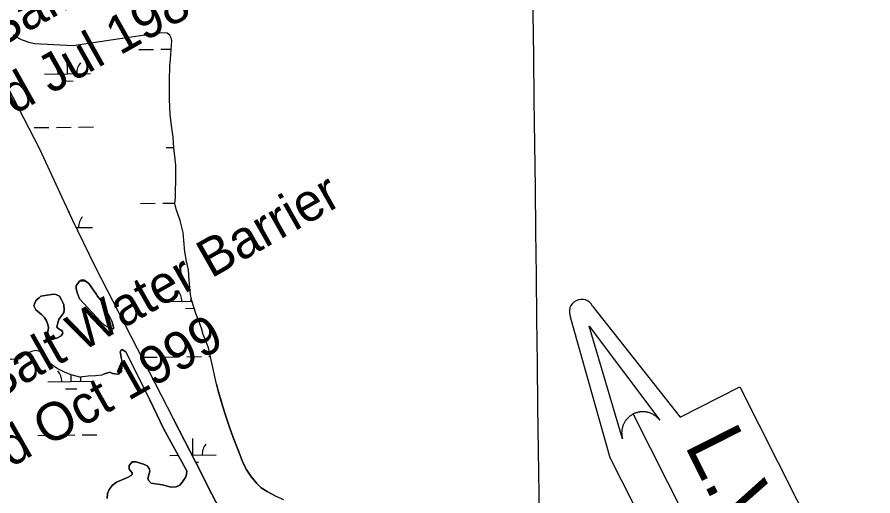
# Model space of a CAD drawing. Extents: x 3684037 to 3722149, y 433263 to 459021.
# Drawn here: x 3713579 to 3715429, y 439834 to 440869 of the extents above; entities that cross this region are included whole.
import ezdxf

# ---------------------------------------------------------------- set-up
doc = ezdxf.new("R2010")
doc.units = 0
for name, color, linetype in [('V-GRID-MAJR', 7, 'Continuous'), ('V-RRAP-SILL-IDEN', 7, 'Continuous'), ('V-TOPO-SHOR', 7, 'Continuous'), ('V-TOPO-WATR-IDEN', 7, 'Continuous'), ('V-WETL-SWMP', 7, 'Continuous')]:
    doc.layers.add(name, color=color, linetype=linetype)

msp = doc.modelspace()

# ---------------------------------------------------------------- linework, layer by layer
at = {"layer": 'V-GRID-MAJR'}
msp.add_spline([(3714717.7800000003, 438985.321), (3714645.519, 445043.8), (3714573.235, 451104.20900000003), (3714500.951, 457164.625), (3714500.9280000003, 457166.547)], degree=3, dxfattribs=at)
at = {"layer": 'V-TOPO-SHOR'}
for points in [[(3714010.265, 440075.83), (3713993.5160000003, 440153.73600000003), (3713987.551, 440169.196), (3713981.585, 440182.871), (3713977.9990000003, 440196.547), (3713972.0330000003, 440211.414), (3713965.469, 440228.656), (3713957.109, 440256.009), (3713954.119, 440269.094), (3713951.702, 440300.619), (3713949.892, 440322.624), (3713945.7060000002, 440341.656), (3713942.112, 440361.876), (3713939.703, 440386.264), (3713938.4930000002, 440403.512), (3713931.919, 440429.68), (3713922.967, 440454.05700000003), (3713920.573, 440465.952), (3713921.7460000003, 440479.04000000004), (3713922.877, 440529.606), (3713922.258, 440549.234), (3713921.054, 440561.724), (3713918.052, 440586.11), (3713916.833, 440609.31), (3713913.8370000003, 440629.529), (3713910.233, 440658.079), (3713909.004, 440691.985), (3713908.955, 440733.029), (3713909.514, 440762.77400000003), (3713911.279, 440778.243), (3713913.612, 440818.101), (3713912.416, 440824.049), (3713910.0300000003, 440828.804), (3713909.434, 440829.994), (3713905.2660000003, 440832.961), (3713903.48, 440834.14900000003), (3713892.177, 440834.731), (3713816.0470000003, 440823.934), (3713700.665, 440807.14), (3713616.785, 440811.206), (3713607.86, 440813.57300000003), (3713588.815, 440820.096), (3713570.9590000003, 440830.186)], [(3713523.423, 440785.515), (3713627.7600000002, 440584.576), (3713698.1350000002, 440431.781), (3713747.603, 440330.726), (3713916.612, 440001.09500000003)], [(3713750.9760000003, 440269.68200000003), (3713734.719, 440292.844), (3713724.278, 440300.367), (3713717.903, 440300.359), (3713713.27, 440297.457), (3713707.485, 440288.175), (3713706.913, 440281.8), (3713709.823, 440271.371), (3713714.474, 440259.786), (3713760.319, 440210.576), (3713768.441, 440203.052), (3713776.56, 440198.425), (3713779.46, 440197.268), (3713782.937, 440196.113), (3713787.576, 440194.96), (3713787.576, 440196.119), (3713787.574, 440197.858), (3713784.659, 440210.025), (3713780.0100000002, 440220.452), (3713773.623, 440232.03500000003), (3713766.074, 440244.778), (3713760.264, 440256.943), (3713752.717, 440266.786), (3713750.9760000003, 440269.68200000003)], [(3713658.242, 440270.151), (3713640.279, 440267.23), (3713631.008, 440265.481), (3713626.955, 440262), (3713620.586, 440257.355), (3713617.696, 440250.977), (3713615.964, 440245.179), (3713620.0330000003, 440235.91000000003), (3713627.574, 440229.545), (3713632.794, 440225.494), (3713638.598, 440219.704), (3713642.663, 440212.755), (3713645.569, 440204.643), (3713647.316, 440197.692), (3713646.167, 440188.99700000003), (3713646.174, 440185.51900000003), (3713649.657, 440178.568), (3713651.9820000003, 440173.936), (3713656.041, 440172.201), (3713659.5160000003, 440173.364), (3713666.469, 440175.691), (3713674.577, 440179.75800000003), (3713678.049, 440186.137), (3713677.465, 440189.033), (3713675.722, 440191.929), (3713672.824, 440193.08400000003), (3713667.022, 440197.135), (3713665.281, 440199.452), (3713666.434, 440205.249), (3713669.3200000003, 440215.684), (3713675.685, 440223.227), (3713678, 440226.706), (3713680.3140000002, 440230.188), (3713681.467, 440235.404), (3713680.293, 440247.57300000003), (3713675.644, 440258), (3713670.9990000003, 440265.528), (3713665.2, 440268.42), (3713662.879, 440269.577), (3713658.242, 440270.151)], [(3713768.642, 440098.106), (3713762.781, 440095.167), (3713749.102, 440093.365), (3713733.04, 440092.753), (3713715.197, 440090.35000000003), (3713696.1550000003, 440095.683), (3713683.6580000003, 440100.427), (3713665.802, 440109.327), (3713649.727, 440120.612), (3713640.196, 440132.498), (3713631.256, 440145.575), (3713619.355, 440148.534), (3713610.436, 440146.14400000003), (3713598.545, 440140.776), (3713585.471, 440130.64900000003), (3713567.627, 440128.843), (3713553.94, 440133.586), (3713541.443, 440137.733), (3713534.8910000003, 440143.08), (3713536.071, 440152.599), (3713547.968, 440153.208), (3713552.127, 440155.594), (3713557.4790000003, 440158.57300000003)], [(3713768.642, 440098.106), (3713779.65, 440101.596), (3713786.0270000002, 440098.706), (3713790.664, 440097.553), (3713795.882, 440096.98), (3713799.937, 440098.723), (3713805.148, 440102.786), (3713805.715, 440113.218), (3713806.282, 440124.231), (3713804.531, 440133.50200000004), (3713802.784, 440141.614), (3713802.201, 440145.669), (3713803.935, 440148.569), (3713805.6720000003, 440149.73), (3713806.251, 440150.31200000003), (3713808.572, 440149.155), (3713814.372, 440145.106), (3713866.6550000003, 440041.42600000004), (3713896.804, 439978.39)], [(3714010.265, 440075.83), (3714014.281, 440061.443), (3714019.096, 440044.723), (3714024.308, 440026.838), (3714029.916, 440008.566), (3714038.7060000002, 439982.523), (3714046.685, 439959.983), (3714057.043, 439932.788), (3714066.984, 439908.70300000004), (3714074.531, 439891.617), (3714084.79, 439876.5), (3714097.389, 439861.015), (3714107.211, 439851.353), (3714119.7490000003, 439843.27), (3714137.364, 439834.06200000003), (3714155.356, 439826.414)], [(3714060.322, 439723.427), (3714000.486, 439837.82), (3713965.748, 439906.246), (3713916.612, 440001.09500000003)], [(3713896.804, 439978.39), (3713943.3140000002, 439893.337), (3713946.2630000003, 439888.27), (3713945.591, 439881.358), (3713944.188, 439875.16500000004), (3713937.008, 439864.2), (3713930.8850000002, 439857.24100000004), (3713923.2800000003, 439853.544), (3713912.014, 439853.088), (3713896.714, 439856.96), (3713888.7, 439858.713), (3713877.7800000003, 439860.442), (3713869.406, 439861.826), (3713863.911, 439866.871), (3713862.0530000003, 439871.581), (3713864.5330000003, 439879.599), (3713866.649, 439887.617), (3713865.146, 439893.42100000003), (3713860.376, 439898.836), (3713852.708, 439902.77), (3713845.784, 439904.896), (3713837.037, 439907.368), (3713828.31, 439907.661), (3713821.833, 439899.608), (3713821.894, 439891.973), (3713824.468, 439888.36), (3713828.505, 439884.031), (3713828.534, 439880.396), (3713826.011, 439877.83), (3713818.046, 439873.764), (3713794.4960000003, 439863.754), (3713784.741, 439856.403), (3713778.628, 439847.99), (3713775.0670000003, 439839.237), (3713774.426, 439828.688)]]:
    msp.add_lwpolyline(points, dxfattribs=at)
at = {"layer": 'V-TOPO-WATR-IDEN'}
msp.add_line((3714911.4286129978, 440011.0038726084), (3715249.903243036, 439340.3800102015), dxfattribs=at)
for points in [[(3714823.368048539, 440244.32581142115), (3715012.440461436, 440004.4185395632), (3715141.6419531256, 440069.6279592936), (3715429.3485540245, 439499.58574517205), (3715300.1470623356, 439434.37632544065), (3715385.3012234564, 439130.94978800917)], [(3715337.9638074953, 439107.058071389), (3715139.659959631, 439365.2558781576), (3715048.004676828, 439546.855397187), (3714909.3357019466, 439476.8676341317), (3714824.145443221, 439645.65779589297), (3714962.8144181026, 439715.64555894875), (3714861.510045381, 439916.3631258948), (3714776.0306325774, 440220.43409480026)]]:
    msp.add_lwpolyline(points, dxfattribs=at)
msp.add_lwpolyline([(3714888.1532795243, 439957.2509763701), (3714815.7278187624, 440200.6222208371), (3714968.500426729, 439997.80138867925), (3714965.564487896, 440001.29808907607), (3714962.4127743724, 440004.3767245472), (3714961.0620843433, 440005.53150026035), (3714959.837528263, 440006.5029443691), (3714958.306520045, 440007.62215886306), (3714956.78795493, 440008.6434796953), (3714955.43981526, 440009.47693976), (3714953.5501225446, 440010.5411389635), (3714951.4659689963, 440011.5844819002), (3714950.2786089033, 440012.1193587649), (3714948.7265896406, 440012.76086672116), (3714946.646862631, 440013.5191256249), (3714945.006765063, 440014.03552877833), (3714943.2205280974, 440014.5252200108), (3714942.0334510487, 440014.8065260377), (3714940.7202833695, 440015.0813203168), (3714939.1065625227, 440015.36236306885), (3714937.613190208, 440015.5714094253), (3714936.1173289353, 440015.72879288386), (3714934.88869454, 440015.82278236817), (3714933.0583915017, 440015.90042119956), (3714931.3034948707, 440015.9052237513), (3714929.9009657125, 440015.8610399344), (3714928.254491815, 440015.7542225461), (3714926.828174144, 440015.61402124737), (3714925.5676337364, 440015.45163550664), (3714924.5928153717, 440015.3023994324), (3714923.108631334, 440015.03049872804), (3714921.595814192, 440014.702141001), (3714920.1743339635, 440014.3459522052), (3714918.740315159, 440013.9347085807), (3714917.424402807, 440013.5125052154), (3714916.0007995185, 440013.007385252), (3714914.8459964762, 440012.5556008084), (3714913.214496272, 440011.8565011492), (3714911.4286129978, 440011.0038726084), (3714910.8655370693, 440010.7146412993), (3714910.0494454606, 440010.2775475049), (3714909.091534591, 440009.73527150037), (3714908.1745485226, 440009.1918077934), (3714907.299175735, 440008.6424631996), (3714906.4566931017, 440008.0878757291), (3714905.4771600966, 440007.408670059), (3714904.804819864, 440006.91979265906), (3714903.8375785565, 440006.1829422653), (3714902.953425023, 440005.47122495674), (3714902.3522467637, 440004.96785709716), (3714900.845930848, 440003.6245653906), (3714900.0658799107, 440002.8796984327), (3714899.5399061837, 440002.35715954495), (3714898.6892610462, 440001.4758495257), (3714897.952364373, 440000.67211229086), (3714897.2029291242, 439999.81332022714), (3714896.3441664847, 439998.7716524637), (3714895.5677400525, 439997.7765813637), (3714894.983065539, 439996.98750407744), (3714894.495944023, 439996.3014300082), (3714893.854843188, 439995.35449655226), (3714893.297954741, 439994.4903913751), (3714892.679258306, 439993.47243473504), (3714892.0747676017, 439992.42300275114), (3714891.4958713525, 439991.3461632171), (3714890.799404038, 439989.95963102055), (3714890.3302641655, 439988.95162852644), (3714889.841428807, 439987.8295116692), (3714889.392153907, 439986.71223940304), (3714889.0501031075, 439985.8019846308), (3714888.698993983, 439984.80314686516), (3714888.2222972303, 439983.30742606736), (3714888.2057413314, 439983.2503436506), (3714887.9474920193, 439982.35382062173), (3714887.769545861, 439981.6876926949), (3714887.520423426, 439980.68320115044), (3714887.2413847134, 439979.4283792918), (3714887.0459275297, 439978.42408962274), (3714886.8890142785, 439977.51654376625), (3714886.713623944, 439976.3493190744), (3714886.5743138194, 439975.2204671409), (3714886.491487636, 439974.4124821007), (3714886.404901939, 439973.35560679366), (3714886.325875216, 439971.89425236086), (3714886.302297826, 439971.0287992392), (3714886.294796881, 439970.3478835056), (3714886.2958045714, 439969.72334909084), (3714886.3093436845, 439968.977442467), (3714886.3445537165, 439967.99884103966), (3714886.4019031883, 439967.01965206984), (3714886.4780001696, 439966.0499251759), (3714886.573507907, 439965.09167532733), (3714886.730436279, 439963.85526409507), (3714886.839203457, 439963.1170947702), (3714887.0388444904, 439961.9392059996), (3714887.3075875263, 439960.5811252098), (3714887.5361085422, 439959.57239301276), (3714887.7234343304, 439958.8150652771), (3714887.908543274, 439958.11206603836), (3714888.049980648, 439957.6054542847)], close=True, dxfattribs=at)
msp.add_arc((3714799.699340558, 440232.3799531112), 26.512473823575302, 26.780582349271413, 206.7805823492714, dxfattribs=at)
at = {"layer": 'V-WETL-SWMP'}
for p, q in [((3713588.8179641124, 440820.0952615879), (3713570.9599719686, 440830.1862626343)), ((3713816.049855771, 440823.93324715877), (3713700.666911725, 440807.141254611)), ((3713892.1788188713, 440834.73124224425), (3713816.049855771, 440823.93324715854)), ((3713903.481813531, 440834.15024153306), (3713892.1788188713, 440834.73124224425)), ((3713909.4358109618, 440829.9932411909), (3713903.481813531, 440834.15024153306)), ((3713912.41680992, 440824.04824105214), (3713909.4358109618, 440829.9932411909)), ((3713913.6138097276, 440818.1012410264), (3713912.41680992, 440824.04824105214)), ((3713607.860955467, 440813.57426043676), (3713588.8179641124, 440820.0952615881)), ((3713616.7869513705, 440811.20525989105), (3713607.860955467, 440813.57426043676)), ((3713700.666911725, 440807.1412546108), (3713616.7869513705, 440811.2052598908)), ((3713911.281813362, 440778.24224151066), (3713913.6138097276, 440818.1012410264)), ((3713842.3843804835, 440798.9505669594), (3713874.382206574, 440799.3229067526)), ((3713890.381119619, 440799.509076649), (3713912.5411404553, 440799.7669397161)), ((3713523.424997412, 440785.51526602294), (3713627.7629605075, 440584.5762611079)), ((3713688.393300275, 440746.41322866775), (3713687.9744158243, 440782.410791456)), ((3713909.5158151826, 440762.77424175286), (3713911.281813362, 440778.24224151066)), ((3713908.9558173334, 440733.0302420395), (3713909.5158151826, 440762.77424175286)), ((3713638.396697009, 440745.83144774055), (3713738.3899035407, 440746.9950095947)), ((3713909.004819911, 440691.9852423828), (3713908.9558173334, 440733.0302420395)), ((3713676.573665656, 440730.8436459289), (3713700.5720352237, 440731.122900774)), ((3713910.2348214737, 440658.0792425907), (3713909.0048199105, 440691.9852423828)), ((3713913.8378215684, 440629.53024260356), (3713910.2348214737, 440658.0792425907)), ((3713616.3334169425, 440630.1348959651), (3713648.3312430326, 440630.5072357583)), ((3713664.3301560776, 440630.6934056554), (3713696.3279821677, 440631.06574544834)), ((3713712.326895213, 440631.2519153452), (3713744.324721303, 440631.62425513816)), ((3713916.8358214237, 440609.3092425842), (3713913.8378215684, 440629.53024260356)), ((3713918.052822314, 440586.1102427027), (3713916.8358214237, 440609.3092425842)), ((3713627.7629605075, 440584.5762611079), (3713698.13793671, 440431.7812579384)), ((3713901.6983107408, 440587.02237541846), (3713917.9950244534, 440587.2120106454)), ((3713921.056822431, 440561.72524271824), (3713918.052822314, 440586.1102427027)), ((3713922.260822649, 440549.23424274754), (3713921.056822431, 440561.72524271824)), ((3713922.878823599, 440529.6052428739), (3713922.260822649, 440549.23424274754)), ((3713921.74882734, 440479.0402433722), (3713922.878823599, 440529.6052428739)), ((3713920.5748287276, 440465.95224355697), (3713921.74882734, 440479.0402433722)), ((3713846.2552800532, 440466.2980891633), (3713878.2531061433, 440466.6704289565)), ((3713894.2520191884, 440466.8565988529), (3713920.6835387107, 440467.16416682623)), ((3713922.9688283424, 440454.0572435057), (3713920.5748287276, 440465.95224355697)), ((3713931.9208256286, 440429.6792431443), (3713922.9688283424, 440454.0572435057)), ((3713691.896825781, 440445.3316790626), (3713691.845315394, 440449.7583136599)), ((3713698.13793671, 440431.7812579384), (3713747.6049195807, 440330.726255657)), ((3713938.494824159, 440403.5132429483), (3713931.9208256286, 440429.6792431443)), ((3713706.8758454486, 440413.93077795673), (3713742.2608031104, 440414.3425317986)), ((3713939.7048246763, 440386.2632430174), (3713938.494824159, 440403.5132429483)), ((3713942.1138250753, 440361.87724307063), (3713939.7048246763, 440386.2632430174)), ((3713945.706824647, 440341.6562430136), (3713942.1138250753, 440361.87724307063)), ((3713747.6049195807, 440330.726255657), (3713916.6148600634, 440001.0952477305)), ((3713949.892823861, 440322.62524290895), (3713945.706824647, 440341.6562430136)), ((3713951.7038243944, 440300.61824298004), (3713949.892823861, 440322.62524290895)), ((3713716.194984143, 440298.59933786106), (3713726.562774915, 440298.71998171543)), ((3713954.1208252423, 440269.09324309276), (3713951.7038243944, 440300.61824298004)), ((3713957.1108246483, 440256.0102430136), (3713954.1208252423, 440269.09324309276)), ((3713905.56921031, 440254.3698976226), (3713957.4277241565, 440254.97334450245)), ((3713955.565813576, 440254.9516785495), (3713955.4699481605, 440263.1900394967)), ((3713965.4708224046, 440228.6562427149), (3713957.1108246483, 440256.0102430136)), ((3713943.746178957, 440239.38209581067), (3713962.1273904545, 440239.5959871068)), ((3713972.0348203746, 440211.4132424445), (3713965.4708224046, 440228.6562427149)), ((3713978.0008184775, 440196.5482421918), (3713972.0348203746, 440211.4132424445)), ((3713981.5868176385, 440182.87124208), (3713978.0008184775, 440196.5482421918)), ((3713987.551815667, 440169.1962418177), (3713981.5868176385, 440182.87124208)), ((3713993.518813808, 440153.73724157), (3713987.551815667, 440169.1962418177)), ((3713598.5470025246, 440140.77626670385), (3713585.472009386, 440130.648267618)), ((3713610.4379965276, 440146.1442659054), (3713598.5470025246, 440140.77626670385)), ((3713619.357992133, 440148.53426532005), (3713610.4379965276, 440146.1442659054)), ((3713631.257986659, 440145.574264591), (3713619.357992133, 440148.53426532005)), ((3713640.1969832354, 440132.49826413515), (3713631.257986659, 440145.574264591)), ((3713803.9369043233, 440148.57025362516), (3713802.201905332, 440145.67025375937)), ((3713802.201905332, 440145.67025375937), (3713802.7859053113, 440141.61425375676)), ((3713802.785905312, 440141.61425375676), (3713804.533904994, 440133.5022537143)), ((3713805.6739034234, 440149.7312535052), (3713803.9369043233, 440148.57025362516)), ((3713806.2529031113, 440150.3122534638), (3713805.6739034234, 440149.7312535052)), ((3713808.5729020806, 440149.1552533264), (3713806.2529031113, 440150.3122534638)), ((3713814.372899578, 440145.1052529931), (3713808.5729020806, 440149.1552533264)), ((3713866.656881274, 440041.4252505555), (3713814.372899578, 440145.1052529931)), ((3714010.2668107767, 440075.83024116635), (3713993.518813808, 440153.73724157)), ((3713585.472009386, 440130.648267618), (3713567.6280179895, 440128.8422687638)), ((3713649.728979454, 440120.61226363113), (3713640.1969832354, 440132.49826413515)), ((3713804.5339049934, 440133.5022537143), (3713806.283904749, 440124.2312536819)), ((3713806.283904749, 440124.2312536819), (3713805.149906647, 440102.7862539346)), ((3713850.126179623, 440133.6456113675), (3713882.124005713, 440134.01795116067)), ((3713898.122918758, 440134.20412105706), (3713930.120744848, 440134.5764608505)), ((3713946.119657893, 440134.7626307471), (3713978.1174839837, 440135.13497054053)), ((3713994.116397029, 440135.32114043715), (3713997.4694131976, 440135.3601575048)), ((3713665.8029725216, 440109.328262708), (3713649.728979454, 440120.61226363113)), ((3713683.6599645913, 440100.4272616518), (3713665.8029725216, 440109.328262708)), ((3713805.149906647, 440102.7862539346), (3713799.938909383, 440098.7232542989)), ((3713696.156958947, 440095.68326090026), (3713683.6599645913, 440100.427261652)), ((3713696.135099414, 440081.10827307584), (3713695.96464855, 440095.75626410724)), ((3713715.198950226, 440090.3512597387), (3713696.156958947, 440095.68326090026)), ((3713733.0419415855, 440092.75225858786), (3713715.198950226, 440090.3512597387)), ((3713749.102933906, 440093.36625756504), (3713733.0419415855, 440092.75225858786)), ((3713762.7819272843, 440095.16725668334), (3713749.102933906, 440093.36625756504)), ((3713768.6429243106, 440098.1062562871), (3713762.7819272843, 440095.16725668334)), ((3713779.6509188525, 440101.5962555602), (3713768.6429243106, 440098.1062562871)), ((3713786.0289160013, 440098.7062551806), (3713779.6509188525, 440101.5962555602)), ((3713790.666913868, 440097.5532548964), (3713786.0289160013, 440098.7062551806)), ((3713795.883911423, 440096.9792545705), (3713790.666913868, 440097.5532548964)), ((3713799.938909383, 440098.7232542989), (3713795.883911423, 440096.9792545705)), ((3713646.1384961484, 440080.52649214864), (3713746.1317026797, 440081.6900540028)), ((3713684.315464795, 440065.538690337), (3713708.3138343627, 440065.8179451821)), ((3714014.2828097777, 440061.44324103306), (3714010.2668107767, 440075.83024116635)), ((3714024.3108072, 440026.83724069), (3714014.282809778, 440061.44324103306)), ((3713896.805870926, 439978.391249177), (3713866.656881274, 440041.4252505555)), ((3714029.9178056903, 440008.5652404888), (3714024.3108071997, 440026.83724069)), ((3713916.6148600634, 440001.0952477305), (3713965.748842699, 439906.2462454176)), ((3714038.706803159, 439982.52424015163), (3714029.9178056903, 440008.5652404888)), ((3713943.3148541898, 439893.33724694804), (3713896.805870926, 439978.391249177)), ((3714046.686800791, 439959.9842398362), (3714038.706803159, 439982.52424015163)), ((3713624.075216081, 439964.8299403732), (3713656.0730421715, 439965.2022801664)), ((3713672.0719552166, 439965.3884500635), (3713704.069781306, 439965.76078985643)), ((3713720.0686943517, 439965.9469597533), (3713752.0665204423, 439966.31929954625)), ((3713959.4367131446, 439922.29920075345), (3713959.0178286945, 439958.29676354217)), ((3714057.0447975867, 439932.78723940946), (3714046.686800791, 439959.9842398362)), ((3713909.4401098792, 439921.71741982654), (3713927.680029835, 439921.92966699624)), ((3713957.4450452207, 439922.27602489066), (3714009.433316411, 439922.8809816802)), ((3714066.9867943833, 439908.7042389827), (3714057.0447975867, 439932.78723940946)), ((3713821.833911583, 439899.60825459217), (3713828.311907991, 439907.66025411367)), ((3713821.8969120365, 439891.9742546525), (3713821.833911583, 439899.60825459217)), ((3713828.311907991, 439907.66025411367), (3713837.038903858, 439907.3682535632)), ((3713837.038903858, 439907.3682535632), (3713845.7848998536, 439904.8952530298)), ((3713845.7848998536, 439904.8952530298), (3713852.7098966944, 439902.77125260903)), ((3713852.7098966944, 439902.77125260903), (3713860.3768932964, 439898.83525215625)), ((3713860.3768932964, 439898.8352521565), (3713865.14789137, 439893.42125189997)), ((3713965.3913027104, 439906.9364461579), (3713971.6154480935, 439907.0088728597)), ((3713965.748842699, 439906.2462454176), (3714000.4868305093, 439837.8192437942)), ((3714074.532791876, 439891.6172386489), (3714066.9867943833, 439908.7042389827)), ((3713824.4709110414, 439888.36025451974), (3713821.8969120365, 439891.9742546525)), ((3713828.505909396, 439884.03025430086), (3713824.4709110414, 439888.36025451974)), ((3713826.0119109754, 439877.82925451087), (3713828.5359096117, 439880.3952543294)), ((3713828.5359096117, 439880.3952543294), (3713828.505909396, 439884.03025430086)), ((3713866.6498910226, 439887.6162518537), (3713864.534892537, 439879.6002520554)), ((3713865.14789137, 439893.42125189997), (3713866.6498910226, 439887.6162518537)), ((3713946.2648531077, 439888.271246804), (3713943.3148541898, 439893.33724694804)), ((3713944.1908549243, 439875.166247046), (3713945.5938538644, 439881.3582469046)), ((3713945.593853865, 439881.3582469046), (3713946.2648531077, 439888.271246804)), ((3714084.7907879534, 439876.50123812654), (3714074.532791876, 439891.6172386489)), ((3713784.742931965, 439856.4032573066), (3713794.497926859, 439863.7542566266)), ((3713794.497926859, 439863.7542566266), (3713818.046915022, 439873.76425504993)), ((3713818.046915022, 439873.76425504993), (3713826.0119109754, 439877.82925451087)), ((3713864.534892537, 439879.6002520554), (3713862.0558942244, 439871.58225228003)), ((3713862.0558942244, 439871.58225228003), (3713863.9128936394, 439866.87125220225)), ((3713863.9128936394, 439866.87125220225), (3713869.407891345, 439861.8262518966)), ((3713869.407891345, 439861.8262518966), (3713888.7018823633, 439858.71325070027)), ((3713930.886862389, 439857.2422480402), (3713937.009859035, 439864.2002475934)), ((3713937.0098590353, 439864.2002475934), (3713944.1908549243, 439875.166247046)), ((3714097.389782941, 439861.015237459), (3714084.7907879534, 439876.50123812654)), ((3713775.0679376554, 439839.2362580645), (3713778.630935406, 439847.9912577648)), ((3713778.630935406, 439847.9912577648), (3713784.742931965, 439856.4032573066)), ((3713888.7018823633, 439858.7132507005), (3713896.7148786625, 439856.9612502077)), ((3713896.7148786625, 439856.96125020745), (3713912.0158716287, 439853.0882492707)), ((3713912.0158716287, 439853.0882492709), (3713923.2828662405, 439853.5442485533)), ((3713923.2828662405, 439853.54424855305), (3713930.886862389, 439857.2422480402)), ((3714107.2127788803, 439851.35223691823), (3714097.389782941, 439861.015237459)), ((3714119.7517734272, 439843.27023619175), (3714107.2127788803, 439851.352236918)), ((3714137.3657656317, 439834.0612351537), (3714119.7517734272, 439843.27023619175)), ((3713774.426938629, 439828.68725819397), (3713775.0679376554, 439839.2362580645)), ((3714000.4868305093, 439837.8192437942), (3714060.324809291, 439723.4262409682))]:
    msp.add_line(p, q, dxfattribs=at)
for points in [[(3713750.975, 440269.681), (3713752.717, 440266.78500000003), (3713760.2630000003, 440256.942), (3713766.073, 440244.778), (3713773.622, 440232.036), (3713780.011, 440220.452), (3713784.66, 440210.025), (3713787.573, 440197.858), (3713787.576, 440194.96), (3713782.938, 440196.114), (3713779.4590000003, 440197.26900000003), (3713776.56, 440198.425), (3713768.441, 440203.05100000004), (3713760.318, 440210.576), (3713714.474, 440259.78500000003), (3713709.823, 440271.371), (3713706.913, 440281.8), (3713707.485, 440288.17600000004), (3713713.27, 440297.456), (3713717.903, 440300.359), (3713724.278, 440300.36600000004), (3713734.719, 440292.844)], [(3713640.2800000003, 440267.231), (3713658.2430000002, 440270.151), (3713662.88, 440269.577), (3713670.9990000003, 440265.529), (3713675.645, 440258), (3713680.293, 440247.574), (3713681.467, 440235.404), (3713680.3140000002, 440230.18700000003), (3713675.686, 440223.226), (3713669.3200000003, 440215.684), (3713666.434, 440205.249), (3713665.282, 440199.452), (3713667.023, 440197.135), (3713672.824, 440193.085), (3713675.723, 440191.93), (3713677.465, 440189.034), (3713678.048, 440186.137), (3713674.578, 440179.757), (3713666.469, 440175.691), (3713656.041, 440172.201), (3713651.9820000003, 440173.935), (3713646.173, 440185.51900000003), (3713646.168, 440188.99700000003), (3713647.3170000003, 440197.692), (3713645.5700000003, 440204.64400000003), (3713642.663, 440212.755), (3713638.598, 440219.705), (3713632.795, 440225.494), (3713627.574, 440229.544), (3713620.032, 440235.911), (3713615.964, 440245.179), (3713617.696, 440250.977), (3713620.586, 440257.355), (3713626.9560000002, 440262), (3713631.009, 440265.482)]]:
    msp.add_lwpolyline(points, close=True, dxfattribs=at)
for centre, radius, start, end in [((3713633.1485924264, 440746.24521397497), 35.24628790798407, 359.89486679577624, 41.438525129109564), ((3713743.626958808, 440747.53078543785), 35.24628790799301, 139.89486415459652, 181.43852248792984), ((3713747.4978583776, 440414.8783076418), 35.24628790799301, 139.89486415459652, 181.43852248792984), ((3713900.3211057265, 440254.78366385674), 35.24628790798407, 359.89486679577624, 41.438525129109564), ((3713640.8903915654, 440080.94025838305), 35.24628790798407, 359.89486679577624, 41.438525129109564), ((3713751.368757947, 440082.22582984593), 35.24628790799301, 166.23602310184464, 181.43852248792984), ((3714014.6703716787, 439923.4167575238), 35.24628790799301, 139.89486415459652, 181.43852248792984)]:
    msp.add_arc(centre, radius, start, end, dxfattribs=at)

# ---------------------------------------------------------------- texts
at = {"layer": 'V-RRAP-SILL-IDEN'}
for s, height, rotation, p in [('Location of Salt Water Barrier', 82.00000000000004, 29.310362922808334, (3712851.871944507, 440798.0714436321)), ('Location of Salt Water Barrier', 82.00000000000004, 29.310362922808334, (3713040.917817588, 440521.42217688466)), ('Constructed Jul 2012', 82.00000000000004, 29.310362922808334, (3712921.386648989, 440674.25017784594)), ('Constructed Jul 1988', 82.00000000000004, 29.310362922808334, (3713110.4325220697, 440397.6009110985)), ('Location of Salt Water Barrier', 82.00000000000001, 29.54090467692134, (3713033.777328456, 439756.4259092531)), ('Constructed Oct 1999', 82.00000000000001, 29.54090467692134, (3713103.789690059, 439632.88535225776))]:
    msp.add_text(s, height=height, rotation=rotation, dxfattribs=at).set_placement(p)
at = {"layer": 'V-TOPO-WATR-IDEN'}
msp.add_text('L.W.R.P.', height=124.4994930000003, rotation=296.78051794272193, dxfattribs=at).set_placement((3715020.870293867, 439943.97550069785))

doc.saveas('drawing.dxf')
